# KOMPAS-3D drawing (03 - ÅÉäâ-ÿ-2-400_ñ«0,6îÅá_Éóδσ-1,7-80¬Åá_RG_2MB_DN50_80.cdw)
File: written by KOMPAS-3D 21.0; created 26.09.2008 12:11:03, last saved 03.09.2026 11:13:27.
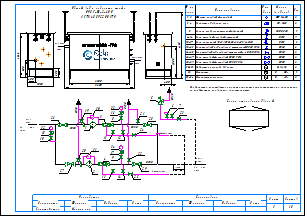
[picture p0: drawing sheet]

Sheets 1-2: A3, landscape

Document properties: Наименование: Макро:21; Автор: RaskoAdmin; Форматы листов документа: 2xA3; Полное имя файла: \\UR38nt01\Departments\КТО\КБ ПУРДГ\Заявки\Прайс-лист на типовые шкафы ГРПШ\ПРДГ_стандарт_20_03_2026\ПРДГ с RG_2MB\ПРДГ-Ш-2-400_до0,6МПа_Рвых-1,7-80кПа_RG_2MB_DN50_80.cdw

Title block, sheet 1: Наименование: Пункт учета газа / ПУГ-Ш-400-Р / ЛГТИ.485922.001ТУ; designation: ЛГТИ.03.4411141; sheet number: 1; Количество листов документа: 2; organisation: ООО "ЭЛЬСТЕР Газэлектроника"; Форматы листов документа: A3; stored path: C:\Рабочие документы\Компас\ПУГ\Схема.cdw; Разработал: Устинов; Проверил: Кошкин; Утвердил: Кошкин
Title block, sheet 2: sheet number: 2; stored path: D:\Рабочие документы\Заявки\ПУРДГ\ПУРДГ-ШУЭО-2-100-Р 4411220.cdw; designation, second copy: ЛГТИ.03.4411141-

Views: Вид 1, Вид 2
Referenced files: wcvoit.frw
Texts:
  Normal
  Вход
  газа
  PDI
  Выход
  Р=     кПа
  DN80
  DN50
  DN20
  Импульс DN20
  ≥5DN
  HYSWLongFangSong
  № на
  схеме
  Усл.
  обозн.
  Марка
  (модель)
  Кол.
  Фильтр газовый фланцевый
  ФГ 16-50
  Регулятор давления газа
  RG/2MB
  Клапан предохранительный сбросной
  КПС DN20
  Кран шаровой газовый латунный
  DN15
  Кран кнопочный VE-РАСКО-НЗ-1,6-G1/2-М20
  Кран шаровой "под приварку" штуцерный DN20 PN16
  Кран шаровой "под приварку" штуцерный п/п DN20 PN16
  Кран шаровой фланцевый DN50 PN16
  Кран шаровой фланцевый DN80 PN16
  Индикатор перепада давления
  Delta 15
  Манометр
  Манометр-напоромер
  0...     МПа
  0...     кПа
  Общий вид и габариты шкафа
  ПРДГ-Ш-2-400
  Выход газа
  Вход газа
  Схема открывания дверей
  Р=        МПа
  logo-rasko-ge.png
  Предприятие изготовитель может заменять комплектующие на аналогичные,
  не ухудшающие заявленных характеристик.
  Должность
  Конструктор
  Фамилия
  Подпись
  Дата
  Согласовано
  Максимкин
  Лист
  Листов
  POLYLINE_STYLE_0.18_RGB_0_0_0
  POLYLINE_STYLE_0.50_RGB_0_0_0
  POLYLINE_STYLE_0.34_RGB_0_0_0
  PHANTOM_RGB_0_0_0_SC_1_THICK_0.18
  K5LT_THIN_RGB_0_0_0_THICK_0.18
  K5LT32769_RGB_0_0_0_THICK_0.18
  K5LT12_RGB_0_0_0_SC_1_THICK_0.18
  K5LT_DASHED_RGB_0_0_0_SC_1_THICK_0.18
  ACISOTGL_RGB_0_0_0_SC_0.8_THICK_0.25
  CONTINUOUS_RGB_0_127_31_THICK_0.3
  CONTINUOUS_RGB_0_0_255_THICK_0.35
  CONTINUOUS_RGB_255_0_0_THICK_0.35
  POLYLINE_STYLE_0.25_RGB_0_0_0
  CONTINUOUS_RGB_0_0_0_THICK_0.5
  POLYLINE_STYLE_0.35_RGB_0_0_255
  CONTINUOUS_RGB_0_0_0_THICK_0.4
  CONTINUOUS_RGB_0_0_0_THICK_0.35
  Без оформления
Dimensions and other numbers on the sheet: 1; 2; 3; 4; 5; 10; 27; 28; 29; 23; 8; 12; 19; 20; 21; 22; 25; 24; 30; 31; 15; 16; 26; 6; 7; 11; 14; 13; 33; 1, 2; 3, 4; 6-14; 9; 15-17; 18-23; 24-25; 26-27; 28-29; 30-31; 32; 33-34; 400; 1050; 500; 305; 2300; 1565; 2600; 17; 34; 1000; 4130; 18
